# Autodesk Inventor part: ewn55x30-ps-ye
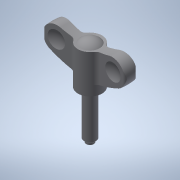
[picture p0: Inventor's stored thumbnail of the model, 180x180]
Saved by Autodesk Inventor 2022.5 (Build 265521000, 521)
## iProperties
Created: 2016-12
Part Number: ewn55x30-ps-ye
Material: 一般
Document SubType Name: Modeling
Designer: imaocorp
Density: 1 g/cm^3
Appearance: 既定
Author: imaocorp
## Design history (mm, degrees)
node "ewn55x30-ps-ye.x_t1"
node "ewn55x30-ps-ye"
node "Base1"
